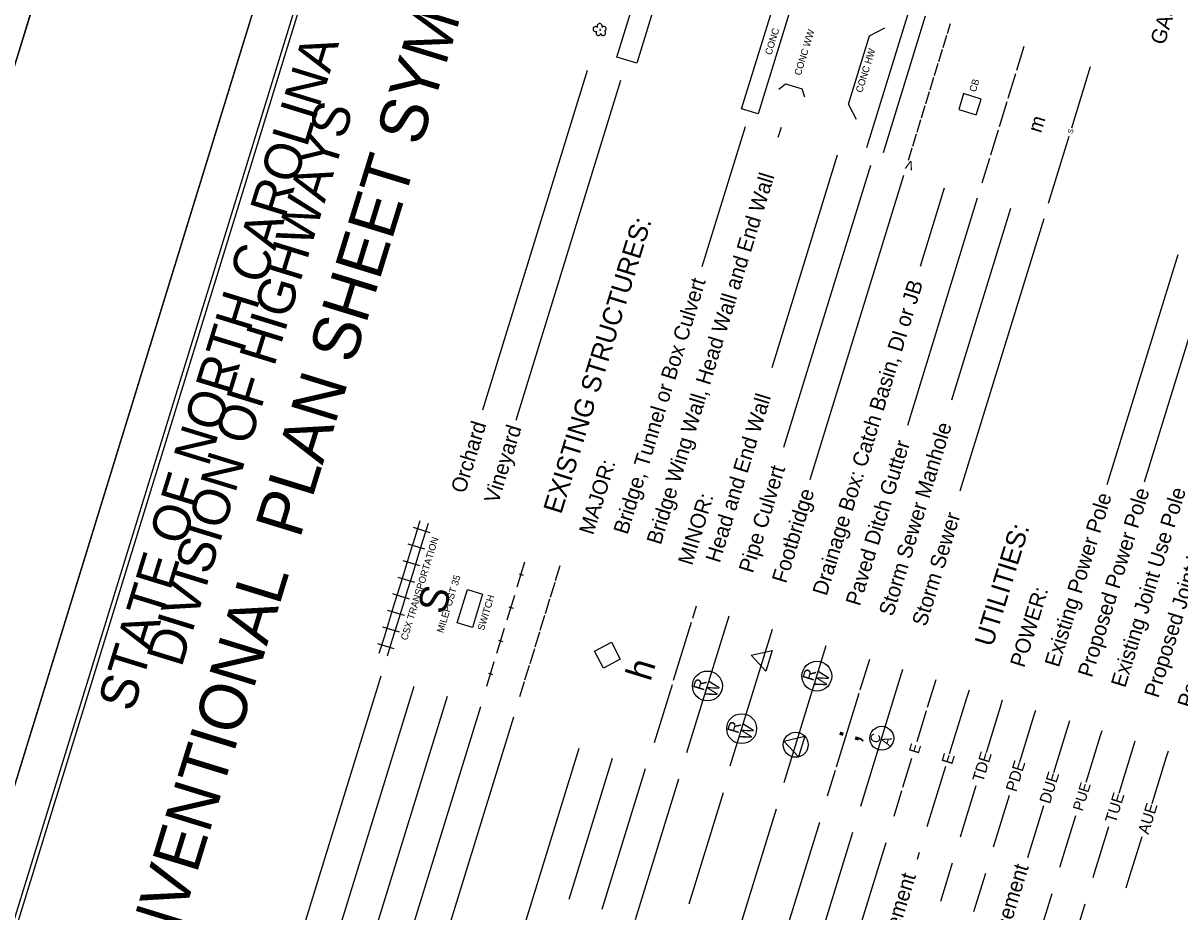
# Model space of a CAD drawing. Extents: x 1347947 to 1350662, y 1027710 to 1030532.
# Drawn here: x 1349324 to 1349990, y 1028788 to 1029300 of the extents above; entities that cross this region are included whole.
import ezdxf

# ---------------------------------------------------------------- set-up
doc = ezdxf.new("R2010")
doc.units = 0
for name, color, linetype in [('Sheet Cutting Line CELL', 7, 'Continuous'), ('Sheet Plot Border Outside CELL', 7, 'Continuous'), ('Sheet Symbology CELL', 7, 'Continuous')]:
    doc.layers.add(name, color=color, linetype=linetype)

msp = doc.modelspace()

# ---------------------------------------------------------------- linework, layer by layer
at = {"layer": 'Sheet Cutting Line CELL'}
msp.add_line((1348998.14, 1028234.22), (1349493.77, 1029843.63), dxfattribs=at)
at = {"layer": 'Sheet Plot Border Outside CELL'}
msp.add_lwpolyline([(1348442.51, 1030167.38), (1347946.88, 1028557.97), (1348998.14, 1028234.22), (1349493.77, 1029843.63)], close=True, dxfattribs=at)
at = {"layer": 'Sheet Symbology CELL'}
for p, q in [((1349610.32, 1029807.71), (1349114.69, 1028198.29)), ((1349809.98, 1029228.61), (1349834.26, 1029307.45)), ((1349819.54, 1029225.66), (1349843.82, 1029304.51)), ((1349856.39, 1029294.36), (1349858.15, 1029300.09)), ((1349799.33, 1029253.47), (1349811.47, 1029292.89)), ((1349811.47, 1029292.89), (1349820.31, 1029297.57)), ((1349853.89, 1029286.24), (1349856.09, 1029293.4)), ((1349896.35, 1029273.16), (1349900.62, 1029287.02)), ((1349851.38, 1029278.11), (1349853.59, 1029285.28)), ((1349648.88, 1029273), (1349588.56, 1029077.14)), ((1349848.88, 1029269.99), (1349851.09, 1029277.16)), ((1349927.96, 1029239.91), (1349938.84, 1029275.24)), ((1349667.99, 1029267.12), (1349607.68, 1029071.26)), ((1349846.38, 1029261.87), (1349848.59, 1029269.03)), ((1349891.35, 1029256.91), (1349895.76, 1029271.25)), ((1349759.18, 1029262.19), (1349763.13, 1029265.27)), ((1349763.13, 1029265.27), (1349772.68, 1029262.33)), ((1349774.21, 1029257.57), (1349772.68, 1029262.33)), ((1349843.88, 1029253.74), (1349846.09, 1029260.91)), ((1349804.01, 1029244.62), (1349799.33, 1029253.47)), ((1349886.34, 1029240.67), (1349890.76, 1029255)), ((1349841.38, 1029245.62), (1349843.59, 1029252.79)), ((1349739.8, 1029240.49), (1349714.95, 1029159.8)), ((1349758.91, 1029234.6), (1349760.68, 1029240.32)), ((1349838.88, 1029237.5), (1349841.08, 1029244.66)), ((1349836.37, 1029229.37), (1349838.58, 1029236.54)), ((1349881.34, 1029224.42), (1349885.75, 1029238.75)), ((1349914.56, 1029196.4), (1349926.49, 1029235.13)), ((1349833.87, 1029221.25), (1349836.08, 1029228.42)), ((1349792.91, 1029224.13), (1349755.15, 1029101.52)), ((1349876.34, 1029208.17), (1349880.75, 1029222.51)), ((1349812.02, 1029218.25), (1349761.93, 1029055.6)), ((1349831.14, 1029212.36), (1349777.14, 1029037.01)), ((1349854.48, 1029205.17), (1349840.59, 1029160.06)), ((1349873.6, 1029199.28), (1349833.29, 1029068.4)), ((1349892.71, 1029193.4), (1349858.67, 1029082.85)), ((1349911.83, 1029187.51), (1349863.5, 1029030.58)), ((1349989.1, 1029166.63), (1349948.28, 1029034.07)), ((1350008.22, 1029160.74), (1349969.69, 1029035.63)), ((1349549.61, 1029003.97), (1349552.55, 1029013.53)), ((1349558.25, 1029006.55), (1349548.69, 1029009.49)), ((1349554.39, 1029002.5), (1349557.33, 1029012.06)), ((1349555.3, 1028996.99), (1349545.75, 1028999.93)), ((1349546.67, 1028994.42), (1349549.61, 1029003.97)), ((1349551.44, 1028992.95), (1349554.39, 1029002.5)), ((1349543.72, 1028984.86), (1349546.67, 1028994.42)), ((1349548.5, 1028983.39), (1349551.44, 1028992.95)), ((1349552.36, 1028987.43), (1349542.8, 1028990.37)), ((1349608.56, 1028975.36), (1349612.97, 1028989.69)), ((1349630.62, 1028979.03), (1349633.27, 1028987.63)), ((1349549.42, 1028977.87), (1349539.86, 1028980.82)), ((1349540.78, 1028975.3), (1349543.72, 1028984.86)), ((1349545.56, 1028973.83), (1349548.5, 1028983.39)), ((1349609.57, 1028982.89), (1349611.96, 1028982.16)), ((1349537.84, 1028965.75), (1349540.78, 1028975.3)), ((1349542.61, 1028964.27), (1349545.56, 1028973.83)), ((1349627.67, 1028969.47), (1349630.32, 1028978.07)), ((1349546.48, 1028968.32), (1349536.92, 1028971.26)), ((1349602.67, 1028956.24), (1349607.09, 1028970.58)), ((1349624.73, 1028959.91), (1349627.38, 1028968.51)), ((1349543.53, 1028958.76), (1349533.97, 1028961.7)), ((1349534.89, 1028956.19), (1349537.84, 1028965.75)), ((1349539.67, 1028954.72), (1349542.61, 1028964.27)), ((1349603.69, 1028963.78), (1349606.07, 1028963.04)), ((1349709.65, 1028957.3), (1349711.86, 1028964.47)), ((1349531.95, 1028946.63), (1349534.89, 1028956.19)), ((1349536.73, 1028945.16), (1349539.67, 1028954.72)), ((1349621.79, 1028950.36), (1349624.44, 1028958.96)), ((1349698.61, 1028921.47), (1349708.91, 1028954.92)), ((1349706.26, 1028879.87), (1349730.54, 1028958.72)), ((1349529.01, 1028937.08), (1349531.95, 1028946.63)), ((1349540.59, 1028949.2), (1349531.03, 1028952.15)), ((1349596.79, 1028937.13), (1349601.2, 1028951.46)), ((1349618.84, 1028940.8), (1349621.49, 1028949.4)), ((1349731.23, 1028872.18), (1349755.51, 1028951.03)), ((1349537.65, 1028939.65), (1349528.09, 1028942.59)), ((1349533.78, 1028935.6), (1349536.73, 1028945.16)), ((1349597.8, 1028944.66), (1349600.19, 1028943.93)), ((1349615.9, 1028931.24), (1349618.55, 1028939.84)), ((1349762.29, 1028862.62), (1349786.57, 1028941.46)), ((1349750.2, 1028933.78), (1349750.2, 1028933.78)), ((1349806.17, 1028915.94), (1349811.66, 1028933.74)), ((1349590.9, 1028918.01), (1349595.31, 1028932.35)), ((1349612.96, 1028921.69), (1349615.61, 1028930.29)), ((1349806.49, 1028849.01), (1349830.77, 1028927.85)), ((1349529.91, 1028923.83), (1349483.29, 1028772.43)), ((1349591.91, 1028925.55), (1349594.3, 1028924.81)), ((1349610.01, 1028912.13), (1349612.66, 1028920.73)), ((1349844.96, 1028905.97), (1349849.88, 1028921.97)), ((1349549.02, 1028917.94), (1349505.01, 1028775.02)), ((1349687.58, 1028885.63), (1349697.88, 1028919.08)), ((1349792.51, 1028871.58), (1349805.59, 1028914.03)), ((1349867.56, 1028911.41), (1349869, 1028916.08)), ((1349568.14, 1028912.06), (1349504.89, 1028706.66)), ((1349857.63, 1028879.15), (1349867.56, 1028911.41)), ((1349886.89, 1028906.23), (1349888.11, 1028910.19)), ((1349587.25, 1028906.17), (1349538.35, 1028747.37)), ((1349606.37, 1028900.28), (1349557.46, 1028741.48)), ((1349606.37, 1028900.28), (1349557.46, 1028741.48)), ((1349838.85, 1028886.14), (1349844.37, 1028904.06)), ((1349878.8, 1028879.95), (1349886.89, 1028906.23)), ((1349898.04, 1028874.49), (1349906.14, 1028900.77)), ((1349906.14, 1028900.77), (1349907.23, 1028904.31)), ((1349917.71, 1028868.43), (1349926.9, 1028898.25)), ((1349936.29, 1028862.75), (1349944.39, 1028889.03)), ((1349944.39, 1028889.03), (1349945.46, 1028892.53)), ((1349963.36, 1028882.68), (1349964.58, 1028886.65)), ((1349644.08, 1028882.25), (1349610.46, 1028773.09)), ((1349768.97, 1028884.31), (1349768.97, 1028884.31)), ((1349955.26, 1028856.4), (1349963.36, 1028882.68)), ((1349982.47, 1028876.79), (1349983.69, 1028880.76)), ((1349663.19, 1028876.36), (1349638.19, 1028795.19)), ((1349830.76, 1028859.86), (1349835.91, 1028876.58)), ((1349974.38, 1028850.51), (1349982.47, 1028876.79)), ((1349682.31, 1028870.48), (1349657.31, 1028789.3)), ((1349787.37, 1028854.89), (1349791.93, 1028869.67)), ((1349845.49, 1028839.73), (1349855.42, 1028871.99)), ((1349701.42, 1028864.59), (1349676.42, 1028783.41)), ((1349864.82, 1028834.55), (1349872.91, 1028860.83)), ((1349727.08, 1028856.69), (1349707.33, 1028792.55)), ((1349825.6, 1028843.12), (1349830.17, 1028857.95)), ((1349884.06, 1028829.09), (1349892.16, 1028855.37)), ((1349757.7, 1028847.26), (1349737.95, 1028783.12)), ((1349902.61, 1028819.4), (1349911.83, 1028849.32)), ((1349844.72, 1028837.23), (1349845.49, 1028839.73)), ((1349922.31, 1028817.35), (1349930.41, 1028843.64)), ((1349782.66, 1028839.57), (1349753.95, 1028746.34)), ((1349801.77, 1028833.69), (1349773.06, 1028740.46)), ((1349863.83, 1028831.35), (1349864.82, 1028834.55)), ((1349941.28, 1028811), (1349949.38, 1028837.28)), ((1349820.89, 1028827.8), (1349792.17, 1028734.57)), ((1349882.95, 1028825.46), (1349884.06, 1028829.09)), ((1349960.4, 1028805.11), (1349968.49, 1028831.4)), ((1349840.11, 1028822.28), (1349838.88, 1028818.29)), ((1349859.11, 1028816.03), (1349852.3, 1028793.9)), ((1349921.18, 1028813.69), (1349922.31, 1028817.35)), ((1349878.23, 1028810.14), (1349871.41, 1028788.02)), ((1349940.3, 1028807.8), (1349941.28, 1028811)), ((1349959.41, 1028801.91), (1349960.4, 1028805.11)), ((1349916.46, 1028798.37), (1349904.06, 1028758.09)), ((1349935.58, 1028792.48), (1349923.18, 1028752.21))]:
    msp.add_line(p, q, dxfattribs=at)
for points in [[(1350165.97, 1027874.54), (1350661.6, 1029483.96), (1349610.32, 1029807.71), (1349114.69, 1028198.29)], [(1350148.34, 1027893.58), (1350638.82, 1029486.26), (1349630.46, 1029796.8), (1349139.98, 1028204.11)], [(1349629.21, 1029784.1), (1349187.74, 1028350.54), (1350190.26, 1028041.81), (1350631.74, 1029475.37)], [(1349873.02, 1029247.32), (1349875.85, 1029256.5), (1349865.69, 1029259.64), (1349862.86, 1029250.45)], [(1349573.96, 1028954.62), (1349579.85, 1028973.74), (1349588.54, 1028971.06), (1349582.66, 1028951.94)], [(1349658.13, 1028928.52), (1349652.95, 1028938.29), (1349662.73, 1028943.47), (1349667.9, 1028933.69)], [(1349751.8, 1028926.75), (1349743.31, 1028935.9), (1349755.48, 1028938.69)], [(1349770.57, 1028877.28), (1349762.09, 1028886.43), (1349774.25, 1028889.23)]]:
    msp.add_lwpolyline(points, close=True, dxfattribs=at)
for points in [[(1349665.9, 1029280.73), (1349689.45, 1029357.18), (1349700.92, 1029353.65), (1349677.37, 1029277.19), (1349665.9, 1029280.73)], [(1349737.76, 1029250.85), (1349762.04, 1029329.69), (1349771.6, 1029326.75), (1349747.31, 1029247.9), (1349737.76, 1029250.85)], [(1349658.86, 1029295.56), (1349659.37, 1029296.03), (1349659.55, 1029296.29), (1349659.69, 1029296.56), (1349659.73, 1029296.86), (1349659.71, 1029297.13), (1349659.64, 1029297.41), (1349659.52, 1029297.71), (1349659.33, 1029297.92), (1349659.12, 1029298.09), (1349658.86, 1029298.28), (1349658.56, 1029298.32), (1349658.26, 1029298.36), (1349657.91, 1029298.26), (1349657.67, 1029298.17), (1349657.46, 1029297.98), (1349657.23, 1029297.73), (1349657.36, 1029298.01), (1349657.47, 1029298.34), (1349657.44, 1029298.61), (1349657.39, 1029298.94), (1349657.32, 1029299.22), (1349657.14, 1029299.49), (1349656.9, 1029299.72), (1349656.62, 1029299.86), (1349656.35, 1029299.99), (1349656.05, 1029300.03), (1349655.73, 1029300.02), (1349655.44, 1029299.91), (1349655.12, 1029299.74), (1349654.91, 1029299.55), (1349654.72, 1029299.29), (1349654.59, 1029299.02), (1349654.5, 1029298.73), (1349654.51, 1029298.42), (1349654.58, 1029298.13), (1349654.69, 1029297.83)], [(1349654.69, 1029297.83), (1349654.45, 1029298.07), (1349654.18, 1029298.2), (1349653.88, 1029298.24), (1349653.58, 1029298.28), (1349653.29, 1029298.21), (1349653.01, 1029298.14), (1349652.75, 1029297.96), (1349652.53, 1029297.77), (1349652.33, 1029297.46), (1349652.26, 1029297.22), (1349652.22, 1029296.92), (1349652.22, 1029296.61), (1349652.29, 1029296.32), (1349652.41, 1029296.03), (1349652.65, 1029295.79), (1349652.86, 1029295.63), (1349653.13, 1029295.49), (1349653.42, 1029295.4), (1349653.72, 1029295.36), (1349654.01, 1029295.43), (1349654.35, 1029295.53), (1349654.13, 1029295.34), (1349654, 1029295.07), (1349653.91, 1029294.78), (1349653.93, 1029294.51), (1349653.95, 1029294.24), (1349654.07, 1029293.95), (1349654.2, 1029293.7), (1349654.4, 1029293.48), (1349654.62, 1029293.36), (1349654.94, 1029293.21), (1349655.2, 1029293.18), (1349655.46, 1029293.2), (1349655.76, 1029293.32), (1349656, 1029293.4), (1349656.21, 1029293.6), (1349656.45, 1029293.84), (1349656.57, 1029294.07), (1349656.66, 1029294.35), (1349656.68, 1029294.08), (1349656.8, 1029293.79), (1349656.94, 1029293.58), (1349657.2, 1029293.4), (1349657.46, 1029293.22), (1349657.7, 1029293.14), (1349658, 1029293.1), (1349658.28, 1029293.17), (1349658.56, 1029293.24), (1349658.81, 1029293.37), (1349659.03, 1029293.57), (1349659.2, 1029293.78), (1349659.29, 1029294.07), (1349659.38, 1029294.35), (1349659.4, 1029294.61), (1349659.28, 1029294.9), (1349659.21, 1029295.19), (1349658.86, 1029295.56)], [(1349656.12, 1029296.51), (1349656.07, 1029296.36), (1349656.09, 1029296.25), (1349656.11, 1029296.14), (1349656.25, 1029296.1), (1349656.35, 1029296.07), (1349656.47, 1029296.14), (1349656.52, 1029296.28), (1349656.55, 1029296.37), (1349656.48, 1029296.5), (1349656.35, 1029296.59), (1349656.24, 1029296.57), (1349656.12, 1029296.51)]]:
    msp.add_lwpolyline(points, dxfattribs=at)
for centre, radius in [((1349718.07, 1028918.22), 8.61), ((1349781.15, 1028923.87), 8.61), ((1349737.83, 1028893.61), 8.61), ((1349818.52, 1028888.07), 6.89), ((1349768.97, 1028884.31), 7.2)]:
    msp.add_circle(centre, radius, dxfattribs=at)

# ---------------------------------------------------------------- texts
for s, height, rotation, p in [('CONVENTIONAL  PLAN SHEET SYMBOLS', 27.2003, 72.88342, (1349392.79, 1028709.05)), ('GAS:', 8.75, 72.88342, (1349981.41, 1029287.22)), ('CONC', 4, 72.88342, (1349754.93, 1029281.59)), ('CONC WW', 4, 72.88344, (1349771.84, 1029269.78)), ('STATE OF NORTH CAROLINA', 21.419, 72.88342, (1349387.02, 1028902.64)), ('CONC HW', 4, 72.88342, (1349807.22, 1029259.85)), ('CB', 4, 72.88342, (1349872.67, 1029260.24)), ('DIVISION OF HIGHWAYS', 21.419, 72.88342, (1349415.01, 1028928.39)), ('m', 8.25, 72.88342, (1349910.32, 1029236.55)), ('S', 3, 72.88342, (1349928.4, 1029236.22)), ('v', 6.6, 162.64256, (1349837.44, 1029220.14)), ('Bridge Wing Wall, Head Wall and End Wall', 8.75, 72.88342, (1349691.17, 1028999.15)), ('EXISTING STRUCTURES:', 11, 72.88342, (1349633.82, 1029016.81)), ('Bridge, Tunnel or Box Culvert', 8.75, 72.88342, (1349672.05, 1029005.04)), ('Drainage Box: Catch Basin, DI or JB', 8.75, 72.88342, (1349786.73, 1028969.73)), ('Head and End Wall', 8.75, 72.88342, (1349725.16, 1028988.68)), ('Orchard', 8.75, 72.88342, (1349578.4, 1029028.77)), ('Vineyard', 8.75, 72.88342, (1349597.51, 1029022.88)), ('Storm Sewer Manhole', 8.75, 72.88342, (1349824.97, 1028957.96)), ('Paved Ditch Gutter', 8.75, 72.88342, (1349805.85, 1028963.84)), ('MAJOR:', 8.75, 72.88342, (1349652.23, 1029004.84)), ('Pipe Culvert', 8.75, 72.88342, (1349744.26, 1028982.8)), ('Proposed Joint Use Pole', 8.75, 72.88342, (1349977.87, 1028910.88)), ('MINOR:', 8.75, 72.88342, (1349709.28, 1028987.27)), ('Footbridge', 8.75, 72.88342, (1349763.38, 1028976.92)), ('Existing Power Pole', 8.75, 72.88342, (1349920.53, 1028928.53)), ('Proposed Power Pole', 8.75, 72.88342, (1349939.64, 1028922.64)), ('Existing Joint Use Pole', 8.75, 72.88342, (1349958.74, 1028916.76)), ('Storm Sewer', 8.75, 72.88342, (1349844.08, 1028952.07)), ('UTILITIES:', 11, 72.88342, (1349882.31, 1028940.29)), ('CSX TRANSPORTATION', 4, 72.88342, (1349545.06, 1028944.23)), ('MILEPOST 35', 4, 72.88342, (1349565.81, 1028948.5)), ('Power Manhole', 8.75, 72.88342, (1349996.99, 1028905)), ('S', 16.5, 72.88342, (1349566.44, 1028958.78)), ('POWER:', 8.75, 72.88342, (1349900.59, 1028928.35)), ('SWITCH', 4, 72.88342, (1349589.25, 1028949.86)), ('h', 15, 72.88342, (1349685.2, 1028920.38)), ('R', 6.75, 72.88342, (1349779.09, 1028920.63)), ('W', 6.75, 72.88342, (1349786.24, 1028916.82)), ('R', 6.75, 72.88342, (1349716.01, 1028914.97)), ('W', 6.75, 72.88342, (1349723.15, 1028911.16)), ('R', 6.75, 72.88342, (1349735.77, 1028890.37)), ('W', 6.75, 72.88342, (1349742.91, 1028886.56)), (';', 15, 72.88342, (1349804.48, 1028884.94)), ('C', 5.4, 72.88342, (1349816.66, 1028884.81)), ('A', 5.4, 72.88342, (1349823.02, 1028883.41)), ('E', 6, 72.88342, (1349839.72, 1028878.76)), ('TDE', 6.55, 72.88342, (1349876.83, 1028862.34)), ('E', 6.55, 72.88342, (1349859.04, 1028872.54)), ('PDE', 6.55, 72.88342, (1349896.05, 1028856.79)), ('DUE', 6.55, 72.88342, (1349915.45, 1028849.87)), ('PUE', 6, 72.88342, (1349934.19, 1028845.72)), ('TUE', 6.55, 72.88342, (1349953.29, 1028838.78)), ('AUE', 6.55, 72.88342, (1349972.21, 1028832.27)), ('Proposed Permanent Drainage /  Utility Easement', 8.75, 72.88342, (1349827.14, 1028566.64)), ('Proposed Temporary Construction Easement', 8.75, 72.88342, (1349769.24, 1028584.47))]:
    msp.add_text(s, height=height, rotation=rotation, dxfattribs=at).set_placement(p)

doc.saveas('drawing.dxf')
